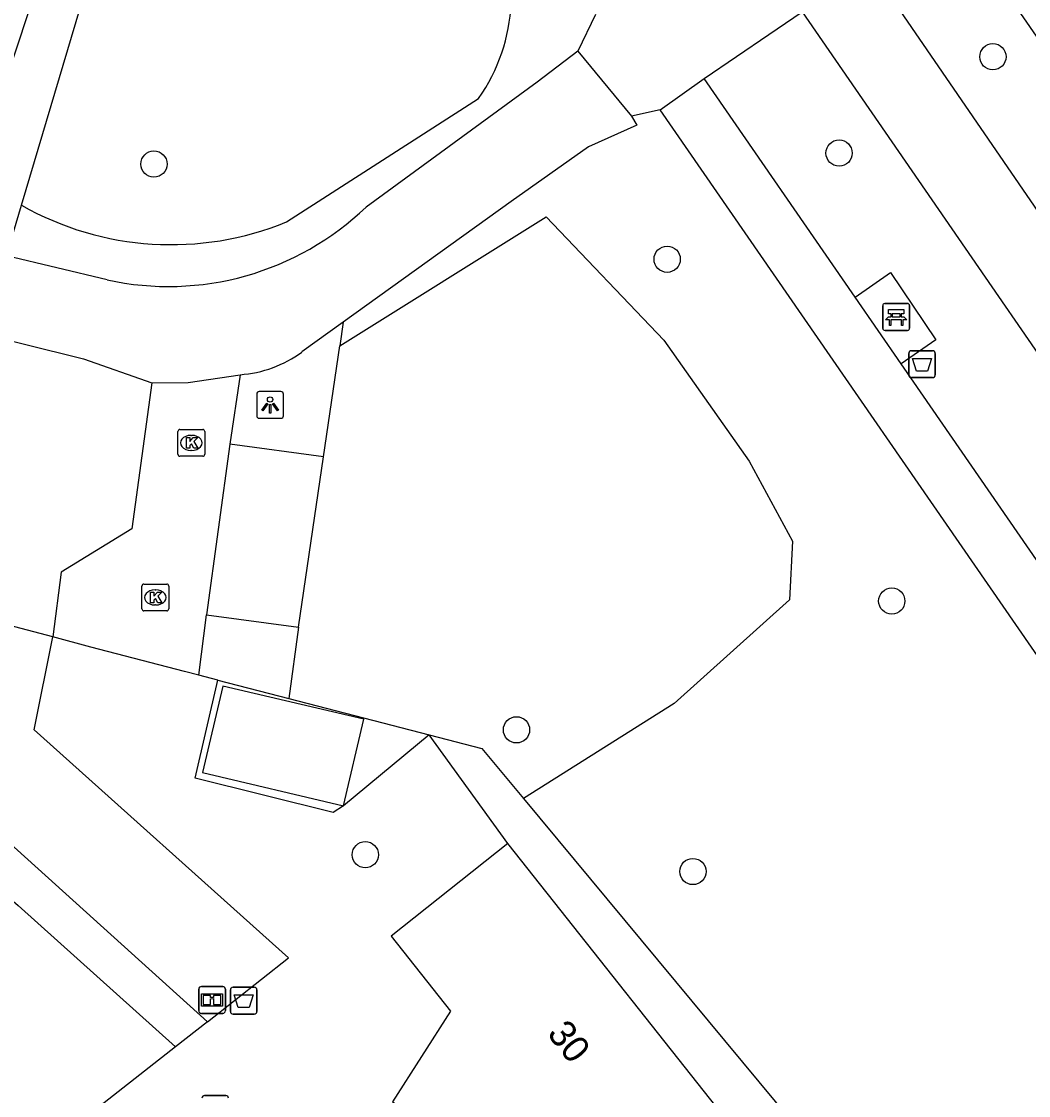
# Model space of a CAD drawing. Extents: x 159888 to 160757, y 384031 to 384746.
# Drawn here: x 160301.51 to 160339.01, y 384175.24 to 384215.24 of the extents above; entities that cross this region are included whole.
import ezdxf

# ---------------------------------------------------------------- set-up
doc = ezdxf.new("R2010")
doc.units = 0
for name, color, linetype in [('IMGEO_Afvalbak', 7, 'Continuous'), ('IMGEO_Bank', 7, 'Continuous'), ('IMGEO_Boom', 7, 'Continuous'), ('IMGEO_Fietspad_gesloten', 7, 'Continuous'), ('IMGEO_Groenvoorziening', 7, 'Continuous'), ('IMGEO_Hek', 7, 'Continuous'), ('IMGEO_Informatiebord', 7, 'Continuous'), ('IMGEO_Kolk', 7, 'Continuous'), ('IMGEO_Lichtpunt', 7, 'Continuous'), ('IMGEO_Pand', 7, 'Continuous'), ('IMGEO_Pand_nummerreeks', 7, 'Continuous'), ('IMGEO_Parkeervlak_open', 7, 'Continuous'), ('IMGEO_Rijbaan_lokaal_open', 7, 'Continuous'), ('IMGEO_Voetpad_gesloten', 7, 'Continuous'), ('IMGEO_Voetpad_halfverhard', 7, 'Continuous'), ('IMGEO_Voetpad_open', 7, 'Continuous')]:
    doc.layers.add(name, color=color, linetype=linetype)

msp = doc.modelspace()

# ---------------------------------------------------------------- linework, layer by layer
at = {"layer": 'IMGEO_Afvalbak'}
for p, q in [((160334.552, 384202.077), (160334.552, 384202.877)), ((160334.552, 384202.877), (160334.552, 384202.077)), ((160334.652, 384202.977), (160335.442, 384202.977)), ((160335.442, 384202.977), (160334.652, 384202.977)), ((160335.542, 384202.877), (160335.542, 384202.077)), ((160335.542, 384202.077), (160335.542, 384202.877)), ((160335.442, 384201.977), (160334.652, 384201.977)), ((160334.652, 384201.977), (160335.442, 384201.977)), ((160309.292, 384178.371), (160309.292, 384179.171)), ((160309.292, 384179.171), (160309.292, 384178.371)), ((160309.392, 384179.271), (160310.182, 384179.271)), ((160310.182, 384179.271), (160309.392, 384179.271)), ((160310.282, 384179.171), (160310.282, 384178.371)), ((160310.282, 384178.371), (160310.282, 384179.171)), ((160310.182, 384178.271), (160309.392, 384178.271)), ((160309.392, 384178.271), (160310.182, 384178.271)), ((160308.333, 384175.238), (160309.123, 384175.238)), ((160309.123, 384175.238), (160308.333, 384175.238))]:
    msp.add_line(p, q, dxfattribs=at)
for points in [[(160334.695, 384202.691), (160335.399, 384202.691), (160335.25, 384202.221), (160334.844, 384202.221), (160334.695, 384202.691)], [(160309.435, 384178.985), (160310.139, 384178.985), (160309.99, 384178.515), (160309.584, 384178.515), (160309.435, 384178.985)]]:
    msp.add_lwpolyline(points, dxfattribs=at)
for centre, start, end in [((160334.652, 384202.877), 90, 180), ((160334.652, 384202.877), 90, 180), ((160335.442, 384202.877), 0, 90), ((160335.442, 384202.877), 360, 90), ((160334.652, 384202.077), 180, 270), ((160334.652, 384202.077), 180, 270), ((160335.442, 384202.077), 270, 0), ((160335.442, 384202.077), 270, 0), ((160309.392, 384179.171), 90, 180), ((160309.392, 384179.171), 90, 180), ((160310.182, 384179.171), 0, 90), ((160310.182, 384179.171), 360, 90), ((160309.392, 384178.371), 180, 270), ((160309.392, 384178.371), 180, 270), ((160310.182, 384178.371), 270, 0), ((160310.182, 384178.371), 270, 0), ((160308.333, 384175.138), 90, 180), ((160308.333, 384175.138), 90, 180), ((160309.123, 384175.138), 0, 90), ((160309.123, 384175.138), 360, 90)]:
    msp.add_arc(centre, 0.1, start, end, dxfattribs=at)
at = {"layer": 'IMGEO_Bank'}
for p, q in [((160333.661, 384204.737), (160334.502, 384204.737)), ((160334.502, 384204.737), (160333.661, 384204.737)), ((160333.586, 384203.812), (160333.586, 384204.653)), ((160333.586, 384204.653), (160333.586, 384203.812)), ((160333.895, 384204.243), (160333.895, 384204.349)), ((160333.939, 384204.349), (160333.939, 384204.243)), ((160334.227, 384204.355), (160333.945, 384204.355)), ((160334.233, 384204.243), (160334.233, 384204.349)), ((160334.277, 384204.349), (160334.277, 384204.243)), ((160334.586, 384204.662), (160334.586, 384203.821)), ((160334.586, 384203.821), (160334.586, 384204.662)), ((160334.283, 384204.135), (160333.89, 384204.135)), ((160333.945, 384204.237), (160334.227, 384204.237)), ((160334.511, 384203.737), (160333.67, 384203.737)), ((160333.67, 384203.737), (160334.511, 384203.737))]:
    msp.add_line(p, q, dxfattribs=at)
for points in [[(160333.889, 384204.355), (160333.803, 384204.355), (160333.803, 384204.516), (160334.366, 384204.516), (160334.366, 384204.355), (160334.283, 384204.355)], [(160333.833, 384204.135), (160333.691, 384204.135), (160333.803, 384204.237), (160333.889, 384204.237)], [(160333.883, 384204.128), (160333.883, 384203.921), (160333.84, 384203.921), (160333.84, 384204.128)], [(160334.283, 384204.237), (160334.366, 384204.237), (160334.478, 384204.135), (160334.339, 384204.135)], [(160334.333, 384204.128), (160334.333, 384203.921), (160334.289, 384203.921), (160334.289, 384204.128)]]:
    msp.add_lwpolyline(points, dxfattribs=at)
for centre, radius, start, end in [((160333.664, 384204.659), 0.0779, 92.4484, 184.2845), ((160333.664, 384204.659), 0.0779, 92.4484, 184.2845), ((160334.508, 384204.659), 0.0779, 2.4484, 94.2845), ((160334.508, 384204.659), 0.0779, 2.4484, 94.2845), ((160333.888, 384204.348), 0.00671, 2.8957, 87.1043), ((160333.945, 384204.348), 0.00671, 92.8957, 177.1043), ((160334.227, 384204.348), 0.00671, 2.8957, 87.1043), ((160334.284, 384204.348), 0.00671, 92.8957, 177.1043), ((160333.833, 384204.128), 0.00671, 2.8957, 87.1043), ((160333.89, 384204.128), 0.00671, 92.8957, 177.1043), ((160333.888, 384204.244), 0.00671, 272.8957, 357.1043), ((160333.945, 384204.244), 0.00671, 182.8957, 267.1043), ((160334.227, 384204.244), 0.00671, 272.8957, 357.1043), ((160334.284, 384204.244), 0.00671, 182.8957, 267.1043), ((160334.282, 384204.128), 0.00671, 2.8957, 87.1043), ((160334.339, 384204.128), 0.00671, 92.8957, 177.1043), ((160333.664, 384203.815), 0.0779, 182.4484, 274.2845), ((160333.664, 384203.815), 0.0779, 182.4484, 274.2845), ((160334.508, 384203.815), 0.0779, 272.4484, 4.2845), ((160334.508, 384203.815), 0.0779, 272.4484, 4.2845)]:
    msp.add_arc(centre, radius, start, end, dxfattribs=at)
at = {"layer": 'IMGEO_Boom'}
for centre in [(160337.687, 384213.928), (160331.96, 384210.341), (160306.446, 384209.931), (160325.558, 384206.386), (160333.922, 384193.656), (160319.946, 384188.858), (160314.317, 384184.205), (160326.517, 384183.58)]:
    msp.add_circle(centre, 0.489, dxfattribs=at)
at = {"layer": 'IMGEO_Fietspad_gesloten'}
for points in [[(160361.72, 384182.176), (160359.923, 384180.881), (160359.126, 384180.306), (160358.513, 384180.285), (160332.952, 384217.524)], [(160330.579, 384215.605), (160356.471, 384178.065)]]:
    msp.add_lwpolyline(points, dxfattribs=at)
at = {"layer": 'IMGEO_Groenvoorziening'}
for points in [[(160300.816, 384212.703), (160278.476, 384220.084), (160284.75, 384239.074), (160307.09, 384231.693), (160300.816, 384212.703)], [(160301.515, 384208.394), (160308.685, 384232.517)], [(160311.382, 384207.777), (160318.536, 384212.371)], [(160300.955, 384206.508), (160301.515, 384208.394)], [(160313.367, 384203.165), (160321.048, 384207.962), (160325.432, 384203.375), (160328.611, 384198.863), (160330.219, 384195.884), (160330.107, 384193.696), (160325.821, 384189.834), (160320.203, 384186.297)], [(160302.678, 384192.316), (160298.712, 384193.366), (160297.903, 384193.58)], [(160316.691, 384188.671), (160318.655, 384188.161), (160320.203, 384186.297)], [(160320.203, 384186.297), (160370.292, 384125.992), (160324.007, 384087.931), (160277.589, 384144.414)]]:
    msp.add_lwpolyline(points, dxfattribs=at)
for centre, radius, start, end in [((160313.001, 384216.249), 6.758, 324.9818, 29.2974), ((160307.084, 384218.245), 11.316, 240.5215, 292.3223)]:
    msp.add_arc(centre, radius, start, end, dxfattribs=at)
at = {"layer": 'IMGEO_Hek'}
for points in [[(160308.828, 384190.712), (160311.464, 384190.028), (160316.691, 384188.671)], [(160316.691, 384188.671), (160318.655, 384188.161), (160320.203, 384186.297), (160370.292, 384125.992), (160324.007, 384087.931), (160277.589, 384144.414)]]:
    msp.add_lwpolyline(points, dxfattribs=at)
at = {"layer": 'IMGEO_Informatiebord'}
for p, q in [((160308.115, 384178.398), (160308.115, 384179.198)), ((160308.115, 384179.198), (160308.115, 384178.398)), ((160308.215, 384179.298), (160309.005, 384179.298)), ((160309.005, 384179.298), (160308.215, 384179.298)), ((160309.105, 384179.198), (160309.105, 384178.398)), ((160309.105, 384178.398), (160309.105, 384179.198)), ((160309.005, 384178.298), (160308.215, 384178.298)), ((160308.215, 384178.298), (160309.005, 384178.298))]:
    msp.add_line(p, q, dxfattribs=at)
for points in [[(160308.216, 384179.03), (160309.004, 384179.03), (160309.004, 384178.566), (160308.216, 384178.566), (160308.216, 384179.03)], [(160308.281, 384178.965), (160308.281, 384178.631), (160308.556, 384178.631), (160308.557, 384178.844), (160308.661, 384178.845), (160308.662, 384178.631), (160308.939, 384178.631), (160308.939, 384178.965), (160308.663, 384178.965), (160308.663, 384178.885), (160308.557, 384178.885), (160308.557, 384178.965), (160308.281, 384178.965)]]:
    msp.add_lwpolyline(points, dxfattribs=at)
for centre, start, end in [((160308.215, 384179.198), 90, 180), ((160308.215, 384179.198), 90, 180), ((160309.005, 384179.198), 0, 90), ((160309.005, 384179.198), 360, 90), ((160308.215, 384178.398), 180, 270), ((160308.215, 384178.398), 180, 270), ((160309.005, 384178.398), 270, 0), ((160309.005, 384178.398), 270, 0)]:
    msp.add_arc(centre, 0.1, start, end, dxfattribs=at)
at = {"layer": 'IMGEO_Kolk'}
for p, q in [((160307.336, 384199.12), (160307.336, 384199.972)), ((160307.411, 384200.046), (160308.263, 384200.046)), ((160308.337, 384199.972), (160308.337, 384199.12)), ((160307.824, 384199.826), (160307.849, 384199.826)), ((160307.847, 384199.266), (160307.822, 384199.266)), ((160308.263, 384199.046), (160307.411, 384199.046)), ((160305.998, 384193.363), (160305.998, 384194.215)), ((160306.073, 384194.289), (160306.925, 384194.289)), ((160306.486, 384194.069), (160306.511, 384194.069)), ((160306.999, 384194.215), (160306.999, 384193.363)), ((160306.925, 384193.289), (160306.073, 384193.289)), ((160306.509, 384193.509), (160306.484, 384193.509))]:
    msp.add_line(p, q, dxfattribs=at)
for points in [[(160307.336, 384199.12), (160307.336, 384199.972)], [(160307.411, 384200.046), (160308.263, 384200.046)], [(160308.337, 384199.972), (160308.337, 384199.12)], [(160307.657, 384199.746), (160307.78, 384199.746), (160307.78, 384199.595), (160307.91, 384199.746), (160308.074, 384199.746), (160307.928, 384199.595), (160308.081, 384199.346), (160307.929, 384199.346), (160307.844, 384199.51), (160307.78, 384199.443), (160307.78, 384199.346), (160307.657, 384199.346), (160307.657, 384199.746)], [(160308.263, 384199.046), (160307.411, 384199.046)], [(160305.998, 384193.363), (160305.998, 384194.215)], [(160306.073, 384194.289), (160306.925, 384194.289)], [(160306.319, 384193.989), (160306.442, 384193.989), (160306.442, 384193.838), (160306.572, 384193.989), (160306.736, 384193.989), (160306.59, 384193.838), (160306.743, 384193.589), (160306.591, 384193.589), (160306.506, 384193.753), (160306.442, 384193.686), (160306.442, 384193.589), (160306.319, 384193.589), (160306.319, 384193.989)], [(160306.999, 384194.215), (160306.999, 384193.363)], [(160306.925, 384193.289), (160306.073, 384193.289)]]:
    msp.add_lwpolyline(points, dxfattribs=at)
for centre, start, end in [((160307.413, 384199.97), 91.552, 178.448), ((160307.413, 384199.97), 91.552, 178.448), ((160308.261, 384199.97), 1.552, 88.448), ((160308.261, 384199.97), 1.552, 88.448), ((160307.413, 384199.122), 181.552, 268.448), ((160307.413, 384199.122), 181.552, 268.448), ((160308.261, 384199.122), 271.552, 358.448), ((160308.261, 384199.122), 271.552, 358.448), ((160306.075, 384194.213), 91.552, 178.448), ((160306.075, 384194.213), 91.552, 178.448), ((160306.923, 384194.213), 1.552, 88.448), ((160306.923, 384194.213), 1.552, 88.448), ((160306.075, 384193.365), 181.552, 268.448), ((160306.075, 384193.365), 181.552, 268.448), ((160306.923, 384193.365), 271.552, 358.448), ((160306.923, 384193.365), 271.552, 358.448)]:
    msp.add_arc(centre, 0.0765, start, end, dxfattribs=at)
for centre, major_axis, ratio, start_param, end_param in [((160307.823, 384199.546), (-0.387, 0.002), 0.722429, 4.712389, 7.853982), ((160307.848, 384199.546), (-0.39, 0.002), 0.717154, 1.570796, 4.712389), ((160306.485, 384193.789), (-0.387, 0.002), 0.722429, 4.712389, 7.853982), ((160306.51, 384193.789), (-0.39, 0.002), 0.717154, 1.570796, 4.712389)]:
    msp.add_ellipse(centre, major_axis=major_axis, ratio=ratio, start_param=start_param, end_param=end_param, dxfattribs=at)
at = {"layer": 'IMGEO_Lichtpunt'}
for p, q in [((160310.272, 384201.364), (160310.272, 384200.557)), ((160310.272, 384201.364), (160310.272, 384200.557)), ((160311.174, 384201.459), (160310.366, 384201.459)), ((160311.174, 384201.459), (160310.366, 384201.459)), ((160311.268, 384200.557), (160311.268, 384201.364)), ((160311.268, 384200.557), (160311.268, 384201.364)), ((160310.366, 384200.463), (160311.174, 384200.463)), ((160310.366, 384200.463), (160311.174, 384200.463))]:
    msp.add_line(p, q, dxfattribs=at)
for points in [[(160310.646, 384201.028), (160310.685, 384201), (160310.497, 384200.738), (160310.459, 384200.765), (160310.646, 384201.028)], [(160310.748, 384200.98), (160310.795, 384200.98), (160310.795, 384200.658), (160310.748, 384200.658), (160310.748, 384200.98)], [(160310.858, 384201), (160310.896, 384201.027), (160311.083, 384200.765), (160311.044, 384200.737), (160310.858, 384201)]]:
    msp.add_lwpolyline(points, dxfattribs=at)
msp.add_circle((160310.771, 384201.162), 0.0994, dxfattribs=at)
for centre, start, end in [((160310.366, 384201.364), 90, 180), ((160310.366, 384201.364), 90, 180), ((160311.174, 384201.364), 0, 90), ((160311.174, 384201.364), 0, 90), ((160310.366, 384200.557), 180, 270), ((160310.366, 384200.557), 180, 270), ((160311.174, 384200.557), 270, 0), ((160311.174, 384200.557), 270, 360)]:
    msp.add_arc(centre, 0.0946, start, end, dxfattribs=at)
at = {"layer": 'IMGEO_Pand'}
for points in [[(160313.504, 384186.027), (160314.264, 384189.253), (160309.017, 384190.49), (160308.257, 384187.264), (160313.504, 384186.027)], [(160319.628, 384184.619), (160315.276, 384181.172), (160317.492, 384178.374), (160315.326, 384175.002), (160323.045, 384170.045), (160323.686, 384170.553), (160324.301, 384169.777), (160328.653, 384173.223)], [(160328.653, 384173.223), (160319.628, 384184.619)]]:
    msp.add_lwpolyline(points, dxfattribs=at)
at = {"layer": 'IMGEO_Parkeervlak_open'}
msp.add_lwpolyline([(160311.827, 384192.684), (160312.759, 384199.028)], dxfattribs=at)
at = {"layer": 'IMGEO_Rijbaan_lokaal_open'}
msp.add_lwpolyline([(160357.438, 384188.412), (160353.761, 384193.768), (160351.005, 384197.748), (160345.217, 384206.146), (160336.597, 384218.641)], dxfattribs=at)
at = {"layer": 'IMGEO_Voetpad_gesloten'}
for points in [[(160322.23, 384214.136), (160320.717, 384212.982), (160314.349, 384208.331)], [(160322.23, 384214.136), (160324.232, 384211.719)], [(160324.232, 384211.719), (160324.433, 384211.38), (160322.632, 384210.572), (160319.754, 384208.536), (160313.496, 384204.041)], [(160268.564, 384211.445), (160272.503, 384210.466), (160303.819, 384202.681), (160306.366, 384201.781)], [(160304.7, 384205.618), (160300.955, 384206.508)], [(160313.496, 384204.041), (160311.951, 384202.931)], [(160306.366, 384201.781), (160307.723, 384201.797), (160309.656, 384202.086)]]:
    msp.add_lwpolyline(points, dxfattribs=at)
for centre, radius, start, end in [((160306.982, 384216.017), 10.646, 257.6219, 313.7868), ((160309.352, 384206.451), 4.376, 273.9855, 306.4411)]:
    msp.add_arc(centre, radius, start, end, dxfattribs=at)
at = {"layer": 'IMGEO_Voetpad_halfverhard'}
for points in [[(160332.555, 384204.976), (160326.934, 384213.116)], [(160377.405, 384134.588), (160370.126, 384146.885), (160361.208, 384159.738), (160341.819, 384188.043), (160325.298, 384211.947)], [(160349.614, 384180.272), (160334.27, 384202.493)]]:
    msp.add_lwpolyline(points, dxfattribs=at)
at = {"layer": 'IMGEO_Voetpad_open'}
for points in [[(160326.934, 384213.116), (160329.34, 384214.759), (160330.579, 384215.605)], [(160322.893, 384215.5), (160322.23, 384214.136)], [(160325.298, 384211.947), (160326.934, 384213.116)], [(160325.298, 384211.947), (160324.232, 384211.719)], [(160332.555, 384204.976), (160333.868, 384205.889), (160335.564, 384203.379), (160334.27, 384202.493)], [(160334.27, 384202.493), (160332.555, 384204.976)], [(160313.496, 384204.041), (160313.367, 384203.165)], [(160312.759, 384199.028), (160313.367, 384203.165)], [(160309.656, 384202.086), (160309.275, 384199.496)], [(160306.366, 384201.781), (160305.619, 384196.347), (160302.995, 384194.731), (160302.678, 384192.316)], [(160309.275, 384199.496), (160308.398, 384193.14)], [(160312.759, 384199.028), (160309.275, 384199.496)], [(160308.118, 384190.896), (160308.398, 384193.14)], [(160308.398, 384193.14), (160311.827, 384192.684)], [(160311.827, 384192.684), (160311.464, 384190.028)], [(160308.437, 384177.986), (160311.461, 384180.361), (160301.985, 384188.857), (160302.678, 384192.316)], [(160308.118, 384190.896), (160307.586, 384191.034), (160304.1, 384191.939), (160302.678, 384192.316)], [(160308.828, 384190.712), (160308.118, 384190.896)], [(160313.504, 384186.027), (160313.118, 384185.773), (160307.976, 384187.053), (160308.828, 384190.712)], [(160308.828, 384190.712), (160311.464, 384190.028)], [(160311.464, 384190.028), (160316.691, 384188.671)], [(160316.691, 384188.671), (160313.504, 384186.027)], [(160319.628, 384184.619), (160316.691, 384188.671)], [(160299.938, 384185.659), (160308.437, 384177.986)], [(160299.803, 384183.751), (160300.158, 384183.369), (160301.391, 384182.317), (160307.246, 384177.051)], [(160308.437, 384177.986), (160307.246, 384177.051)], [(160307.246, 384177.051), (160295.871, 384168.118)]]:
    msp.add_lwpolyline(points, dxfattribs=at)

# ---------------------------------------------------------------- texts
at = {"layer": 'IMGEO_Pand_nummerreeks'}
msp.add_text('30', height=1, rotation=308.3765, dxfattribs=at).set_placement((160321.058, 384177.53))

doc.saveas('drawing.dxf')
